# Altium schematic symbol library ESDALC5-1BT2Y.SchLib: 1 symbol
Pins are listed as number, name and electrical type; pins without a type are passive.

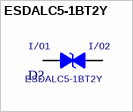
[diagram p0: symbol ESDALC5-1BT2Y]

## ESDALC5-1BT2Y
designator D?
footprint ST_SOD882TB
pins: 1 I/O1, 2 I/O2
